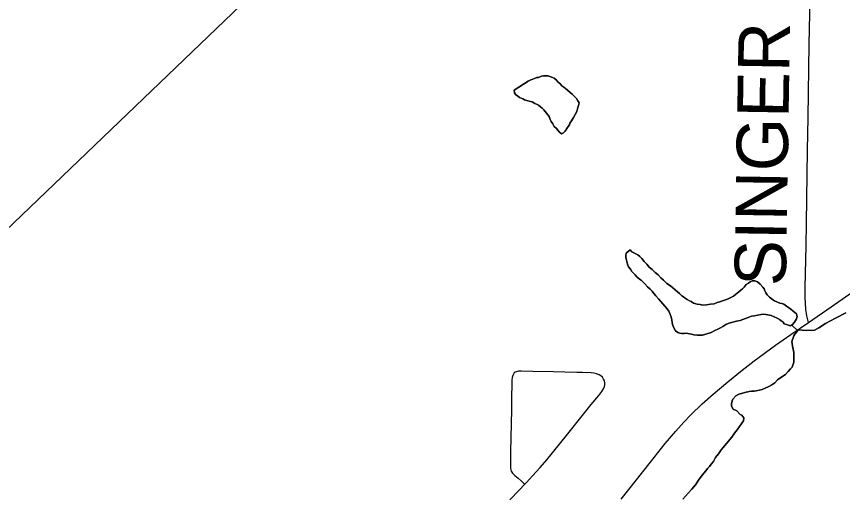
# Model space of a CAD drawing. Extents: x 0 to 34, y 0 to 22.
# Drawn here: x 23.893 to 24.806, y 14.723 to 15.253 of the extents above; entities that cross this region are included whole.
import ezdxf

# ---------------------------------------------------------------- set-up
doc = ezdxf.new("R2010")
doc.units = 0
for name, color, linetype in [('GM_X_Major_River', 7, 'Continuous'), ('GM_X_Minor_Lake', 7, 'Continuous'), ('GM_X_Minor_River', 7, 'Continuous'), ('GM_X_State_Route', 7, 'Continuous'), ('GM_X_Township_Road', 7, 'Continuous'), ('GM_X_Township_Road_Text', 7, 'Continuous')]:
    doc.layers.add(name, color=color, linetype=linetype)

msp = doc.modelspace()

# ---------------------------------------------------------------- linework, layer by layer
at = {"layer": 'GM_X_Major_River'}
for points in [[(24.81011, 14.92539), (24.79851, 14.91969), (24.78765, 14.91358), (24.78026, 14.90888), (24.77523, 14.90638), (24.77255, 14.90609), (24.76989, 14.90618), (24.76607, 14.90592), (24.7619, 14.90644), (24.7581, 14.90657), (24.75574, 14.90436), (24.75375, 14.90176), (24.75255, 14.8999), (24.75173, 14.89803), (24.75091, 14.89615), (24.75044, 14.8935), (24.75076, 14.89159), (24.75105, 14.88854), (24.75171, 14.88547), (24.75203, 14.88356), (24.75235, 14.88165), (24.75267, 14.87973), (24.75257, 14.87669), (24.75246, 14.87327), (24.75239, 14.87099), (24.75194, 14.86873), (24.75069, 14.86534), (24.74872, 14.8635), (24.74634, 14.86054), (24.74319, 14.85722), (24.7393, 14.85469), (24.73463, 14.85141), (24.73147, 14.8481), (24.72836, 14.84592), (24.72487, 14.84413), (24.72101, 14.84236), (24.71753, 14.84095), (24.71408, 14.83992), (24.71101, 14.83926), (24.70871, 14.83896), (24.70567, 14.83906), (24.70299, 14.83877), (24.69838, 14.8374), (24.69454, 14.83638), (24.69185, 14.83571), (24.68837, 14.83393), (24.6852, 14.83023), (24.68438, 14.82835), (24.68351, 14.82496), (24.68381, 14.82228), (24.68561, 14.81918), (24.68935, 14.81715), (24.69304, 14.81323), (24.69492, 14.8124), (24.69711, 14.80967), (24.697, 14.80625), (24.69502, 14.80365), (24.69261, 14.79992), (24.68983, 14.79621), (24.68704, 14.7925), (24.68385, 14.78804), (24.67237, 14.77434), (24.66918, 14.76988), (24.66601, 14.7658)], [(24.66601, 14.7658), (24.66918, 14.76988), (24.67237, 14.77434), (24.68385, 14.78804), (24.68704, 14.7925), (24.68983, 14.79621), (24.69261, 14.79992), (24.69502, 14.80365), (24.697, 14.80625), (24.69711, 14.80967), (24.69492, 14.8124), (24.69304, 14.81323), (24.68935, 14.81715), (24.68561, 14.81918), (24.68381, 14.82228), (24.68351, 14.82496), (24.68438, 14.82835), (24.6852, 14.83023), (24.68837, 14.83393), (24.69185, 14.83571), (24.69454, 14.83638), (24.69838, 14.8374), (24.70299, 14.83877), (24.70567, 14.83906), (24.70871, 14.83896), (24.71101, 14.83926), (24.71408, 14.83992), (24.71753, 14.84095), (24.72101, 14.84236), (24.72487, 14.84413), (24.72836, 14.84592), (24.73147, 14.8481), (24.73463, 14.85141), (24.7393, 14.85469), (24.74319, 14.85722), (24.74634, 14.86054), (24.74872, 14.8635), (24.75069, 14.86534), (24.75194, 14.86873), (24.75239, 14.87099), (24.75246, 14.87327), (24.75257, 14.87669), (24.75267, 14.87973), (24.75235, 14.88165), (24.75203, 14.88356), (24.75171, 14.88547), (24.75105, 14.88854), (24.75076, 14.89159), (24.75044, 14.8935), (24.75091, 14.89615), (24.75173, 14.89803), (24.75255, 14.8999), (24.75375, 14.90176), (24.75574, 14.90436), (24.7581, 14.90657), (24.7619, 14.90644), (24.76607, 14.90592), (24.76989, 14.90618), (24.77255, 14.90609), (24.77523, 14.90638), (24.78026, 14.90888), (24.78765, 14.91358), (24.79851, 14.91969), (24.81011, 14.92539)], [(24.66601, 14.7658), (24.66358, 14.76132), (24.6612, 14.75835), (24.65921, 14.75576), (24.65724, 14.75354), (24.65525, 14.75094), (24.65288, 14.74836), (24.6501, 14.74465), (24.6473, 14.74055), (24.64372, 14.73573), (24.63975, 14.73091), (24.63581, 14.72648), (24.62988, 14.71983)], [(24.62988, 14.71983), (24.63581, 14.72648), (24.63975, 14.73091), (24.64372, 14.73573), (24.6473, 14.74055), (24.6501, 14.74465), (24.65288, 14.74836), (24.65525, 14.75094), (24.65724, 14.75354), (24.65921, 14.75576), (24.6612, 14.75835), (24.66358, 14.76132), (24.66601, 14.7658)]]:
    msp.add_lwpolyline(points, dxfattribs=at)
at = {"layer": 'GM_X_Minor_Lake'}
for points in [[(24.50687, 15.13746), (24.50808, 15.13932), (24.5089, 15.1412), (24.51254, 15.14792), (24.51382, 15.15207), (24.51465, 15.15432), (24.51513, 15.15735), (24.51368, 15.15968), (24.51223, 15.16201), (24.51002, 15.16437), (24.50743, 15.16673), (24.50521, 15.16871), (24.50225, 15.17147), (24.50001, 15.17307), (24.49816, 15.17465), (24.49631, 15.17623), (24.49446, 15.1782), (24.49187, 15.18057), (24.49003, 15.18253), (24.48781, 15.18451), (24.48593, 15.18533), (24.48293, 15.18657), (24.48066, 15.18703), (24.47799, 15.18712), (24.47571, 15.18719), (24.47379, 15.18687), (24.47032, 15.18547), (24.46841, 15.18515), (24.46609, 15.18409), (24.46416, 15.18339), (24.46185, 15.18271), (24.45876, 15.18129), (24.44359, 15.17114)], [(24.44359, 15.17114), (24.45876, 15.18129), (24.46185, 15.18271), (24.46416, 15.18339), (24.46609, 15.18409), (24.46841, 15.18515), (24.47032, 15.18547), (24.47379, 15.18687), (24.47571, 15.18719), (24.47799, 15.18712), (24.48066, 15.18703), (24.48293, 15.18657), (24.48593, 15.18533), (24.48781, 15.18451), (24.49003, 15.18253), (24.49187, 15.18057), (24.49446, 15.1782), (24.49631, 15.17623), (24.49816, 15.17465), (24.50001, 15.17307), (24.50225, 15.17147), (24.50521, 15.16871), (24.50743, 15.16673), (24.51002, 15.16437), (24.51223, 15.16201), (24.51368, 15.15968), (24.51513, 15.15735), (24.51465, 15.15432), (24.51382, 15.15207), (24.51254, 15.14792), (24.5089, 15.1412), (24.50808, 15.13932), (24.50687, 15.13746), (24.50489, 15.13486), (24.50445, 15.13297), (24.50325, 15.13111), (24.50165, 15.12888), (24.49965, 15.1259), (24.49807, 15.12406), (24.49575, 15.12299), (24.49316, 15.12536), (24.49022, 15.12888), (24.48764, 15.13125), (24.4862, 15.13396), (24.48438, 15.13668), (24.48331, 15.139), (24.48227, 15.14208), (24.48081, 15.14403), (24.47935, 15.14598), (24.47641, 15.1495), (24.47457, 15.15147), (24.47271, 15.15305), (24.47048, 15.15465), (24.46824, 15.15586), (24.46636, 15.15669), (24.46336, 15.15831), (24.46147, 15.15875), (24.45845, 15.15961), (24.45505, 15.16048), (24.45319, 15.16169), (24.44943, 15.16333), (24.4472, 15.16493), (24.44533, 15.16613), (24.44388, 15.16846), (24.44359, 15.17114)], [(24.44359, 15.17114), (24.44388, 15.16846), (24.44533, 15.16613), (24.4472, 15.16493), (24.44943, 15.16333), (24.45319, 15.16169), (24.45505, 15.16048), (24.45845, 15.15961), (24.46147, 15.15875), (24.46336, 15.15831), (24.46636, 15.15669), (24.46824, 15.15586), (24.47048, 15.15465), (24.47271, 15.15305), (24.47457, 15.15147), (24.47641, 15.1495), (24.47935, 15.14598), (24.48081, 15.14403), (24.48227, 15.14208), (24.48331, 15.139), (24.48438, 15.13668), (24.4862, 15.13396), (24.48764, 15.13125), (24.49022, 15.12888), (24.49316, 15.12536), (24.49575, 15.12299), (24.49807, 15.12406), (24.49965, 15.1259), (24.50165, 15.12888), (24.50325, 15.13111), (24.50445, 15.13297), (24.50489, 15.13486), (24.50687, 15.13746)], [(24.57164, 14.99492), (24.56733, 14.99126), (24.56688, 14.98899), (24.5668, 14.98671), (24.56748, 14.98403), (24.56779, 14.98173), (24.5692, 14.97826), (24.5699, 14.97634), (24.5721, 14.9736), (24.57355, 14.97127), (24.57539, 14.96931), (24.57723, 14.96734), (24.57907, 14.96538), (24.58203, 14.96262), (24.5839, 14.96141), (24.58575, 14.95983), (24.58796, 14.95748), (24.59091, 14.95434), (24.59387, 14.95157), (24.59608, 14.94922), (24.5979, 14.94688), (24.6001, 14.94414), (24.60305, 14.941), (24.6126, 14.93003), (24.61442, 14.92731), (24.61547, 14.92461), (24.61653, 14.92191), (24.61722, 14.9196), (24.61753, 14.91731), (24.61821, 14.915), (24.61852, 14.91271), (24.61922, 14.91079), (24.61992, 14.90886), (24.62173, 14.90576), (24.62433, 14.90377), (24.62659, 14.90293), (24.62886, 14.90248), (24.63115, 14.90278), (24.63307, 14.9031), (24.63534, 14.90264), (24.63761, 14.90219), (24.6395, 14.90174), (24.64215, 14.90128), (24.64556, 14.90078), (24.64861, 14.90068), (24.65166, 14.90096), (24.65512, 14.90199)], [(24.65512, 14.90199), (24.65166, 14.90096), (24.64861, 14.90068), (24.64556, 14.90078), (24.64215, 14.90128), (24.6395, 14.90174), (24.63761, 14.90219), (24.63534, 14.90264), (24.63307, 14.9031), (24.63115, 14.90278), (24.62886, 14.90248), (24.62659, 14.90293), (24.62433, 14.90377), (24.62173, 14.90576), (24.61992, 14.90886), (24.61922, 14.91079), (24.61852, 14.91271), (24.61821, 14.915), (24.61753, 14.91731), (24.61722, 14.9196), (24.61653, 14.92191), (24.61547, 14.92461), (24.61442, 14.92731), (24.6126, 14.93003), (24.60305, 14.941), (24.6001, 14.94414), (24.5979, 14.94688), (24.59608, 14.94922), (24.59387, 14.95157), (24.59091, 14.95434), (24.58796, 14.95748), (24.58575, 14.95983), (24.5839, 14.96141), (24.58203, 14.96262), (24.57907, 14.96538), (24.57723, 14.96734), (24.57539, 14.96931), (24.57355, 14.97127), (24.5721, 14.9736), (24.5699, 14.97634), (24.5692, 14.97826), (24.56779, 14.98173), (24.56748, 14.98403), (24.5668, 14.98671), (24.56688, 14.98899), (24.56733, 14.99126), (24.57164, 14.99492)], [(24.65512, 14.90199), (24.66127, 14.90369), (24.66515, 14.90584), (24.66862, 14.90725), (24.67134, 14.90906), (24.67405, 14.91049), (24.67755, 14.91266), (24.67987, 14.91372), (24.68218, 14.91441), (24.68525, 14.91507), (24.68909, 14.91608), (24.69331, 14.91708), (24.69909, 14.91917), (24.70217, 14.92021), (24.70564, 14.92162), (24.70909, 14.92227), (24.71254, 14.92291), (24.71637, 14.92355), (24.71942, 14.92383), (24.7217, 14.92375), (24.7236, 14.92331), (24.72548, 14.92286), (24.72737, 14.92242), (24.73414, 14.91953), (24.73675, 14.91792), (24.73862, 14.91672), (24.74085, 14.91513), (24.74193, 14.91319), (24.74458, 14.91272), (24.74872, 14.91106), (24.75105, 14.91251), (24.75342, 14.91509), (24.75544, 14.91883), (24.75629, 14.92146), (24.75562, 14.92453), (24.75376, 14.92573), (24.7519, 14.92731), (24.74931, 14.92968), (24.7467, 14.93129), (24.74447, 14.93289), (24.74148, 14.93489), (24.73922, 14.93573), (24.73695, 14.93618), (24.73132, 14.93865), (24.72908, 14.94025), (24.72574, 14.94264), (24.72316, 14.94539), (24.72171, 14.94772), (24.72063, 14.94966), (24.71956, 14.95198), (24.7181, 14.95393), (24.71515, 14.95707), (24.71219, 14.95983), (24.70955, 14.96068), (24.70651, 14.96078), (24.70419, 14.95971), (24.70224, 14.95826), (24.69991, 14.95681), (24.69753, 14.95385), (24.69595, 14.952), (24.694, 14.95054), (24.69165, 14.94871), (24.68813, 14.94579), (24.68579, 14.94396), (24.68307, 14.94253), (24.67997, 14.94073), (24.67689, 14.93969), (24.67381, 14.93865), (24.67073, 14.93761), (24.66766, 14.93695), (24.66457, 14.93553), (24.66036, 14.93491), (24.65615, 14.93429), (24.65196, 14.93405), (24.64893, 14.93453), (24.64551, 14.93502), (24.64175, 14.93629), (24.63913, 14.9379), (24.63725, 14.93872), (24.63464, 14.94033), (24.63239, 14.94155), (24.63054, 14.94313), (24.62867, 14.94433), (24.62608, 14.9467), (24.62386, 14.94868), (24.61608, 14.9554), (24.61235, 14.95781), (24.60865, 14.96136), (24.60569, 14.96412), (24.60275, 14.96726), (24.59941, 14.97003), (24.59608, 14.97319), (24.59274, 14.97596), (24.59018, 14.97909), (24.58723, 14.98223), (24.58466, 14.98536), (24.58245, 14.98772), (24.58022, 14.98931), (24.57722, 14.99093), (24.57348, 14.99296), (24.57164, 14.99492)], [(24.57164, 14.99492), (24.57348, 14.99296), (24.57722, 14.99093), (24.58022, 14.98931), (24.58245, 14.98772), (24.58466, 14.98536), (24.58723, 14.98223), (24.59018, 14.97909), (24.59274, 14.97596), (24.59608, 14.97319), (24.59941, 14.97003), (24.60275, 14.96726), (24.60569, 14.96412), (24.60865, 14.96136), (24.61235, 14.95781), (24.61608, 14.9554), (24.62386, 14.94868), (24.62608, 14.9467), (24.62867, 14.94433), (24.63054, 14.94313), (24.63239, 14.94155), (24.63464, 14.94033), (24.63725, 14.93872), (24.63913, 14.9379), (24.64175, 14.93629), (24.64551, 14.93502), (24.64893, 14.93453), (24.65196, 14.93405), (24.65615, 14.93429), (24.66036, 14.93491), (24.66457, 14.93553), (24.66766, 14.93695), (24.67073, 14.93761), (24.67381, 14.93865), (24.67689, 14.93969), (24.67997, 14.94073), (24.68307, 14.94253), (24.68579, 14.94396), (24.68813, 14.94579), (24.69165, 14.94871), (24.694, 14.95054), (24.69595, 14.952), (24.69753, 14.95385), (24.69991, 14.95681), (24.70224, 14.95826), (24.70419, 14.95971), (24.70651, 14.96078), (24.70955, 14.96068), (24.71219, 14.95983), (24.71515, 14.95707), (24.7181, 14.95393), (24.71956, 14.95198), (24.72063, 14.94966), (24.72171, 14.94772), (24.72316, 14.94539), (24.72574, 14.94264), (24.72908, 14.94025), (24.73132, 14.93865), (24.73695, 14.93618), (24.73922, 14.93573), (24.74148, 14.93489), (24.74447, 14.93289), (24.7467, 14.93129), (24.74931, 14.92968), (24.7519, 14.92731), (24.75376, 14.92573), (24.75562, 14.92453), (24.75629, 14.92146), (24.75544, 14.91883), (24.75342, 14.91509), (24.75105, 14.91251), (24.74872, 14.91106), (24.74458, 14.91272), (24.74193, 14.91319), (24.74085, 14.91513), (24.73862, 14.91672), (24.73675, 14.91792), (24.73414, 14.91953), (24.72737, 14.92242), (24.72548, 14.92286), (24.7236, 14.92331), (24.7217, 14.92375), (24.71942, 14.92383), (24.71637, 14.92355), (24.71254, 14.92291), (24.70909, 14.92227), (24.70564, 14.92162), (24.70217, 14.92021), (24.69909, 14.91917), (24.69331, 14.91708), (24.68909, 14.91608), (24.68525, 14.91507), (24.68218, 14.91441), (24.67987, 14.91372), (24.67755, 14.91266), (24.67405, 14.91049), (24.67134, 14.90906), (24.66862, 14.90725), (24.66515, 14.90584), (24.66127, 14.90369), (24.65512, 14.90199)]]:
    msp.add_lwpolyline(points, dxfattribs=at)
at = {"layer": 'GM_X_Minor_River'}
for p, q in [((23.51667, 14.66697), (25.12417, 16.20645)), ((24.75016, 14.91194), (24.75696, 14.9055))]:
    msp.add_line(p, q, dxfattribs=at)
at = {"layer": 'GM_X_State_Route'}
msp.add_lwpolyline([(24.56172, 14.71971), (24.59428, 14.7606), (24.61049, 14.78101), (24.62208, 14.79487), (24.63078, 14.80464), (24.63851, 14.81278), (24.65114, 14.82481), (24.66325, 14.83556), (24.67943, 14.84918), (24.69537, 14.86214), (24.70866, 14.87243), (24.73228, 14.88966), (24.74915, 14.90136), (24.76861, 14.91477), (24.7937, 14.93204), (24.81816, 14.94913)], dxfattribs=at)
at = {"layer": 'GM_X_Township_Road'}
for points in [[(24.76861, 14.91477), (24.76689, 14.92196), (24.76573, 14.92936), (24.76523, 14.93594), (24.76494, 14.94287), (24.76498, 14.95344), (24.76615, 14.99945), (24.76645, 15.02432), (24.76751, 15.10517), (24.76837, 15.14124), (24.76961, 15.22209), (24.77211, 15.33962), (24.77246, 15.35766), (24.77329, 15.39746), (24.77349, 15.40803), (24.77361, 15.41489)], [(24.43856, 14.71901), (24.44899, 14.72966), (24.45511, 14.73617), (24.45706, 14.73825), (24.4638, 14.74558), (24.4723, 14.75462), (24.47963, 14.76304), (24.50141, 14.79016), (24.52007, 14.81345), (24.52865, 14.8241), (24.53699, 14.83411), (24.5404, 14.83848), (24.5423, 14.84149), (24.54337, 14.84418), (24.54373, 14.84585), (24.5438, 14.84812), (24.5433, 14.85031), (24.54235, 14.85239), (24.54101, 14.85425), (24.5393, 14.85578), (24.53731, 14.85697), (24.53455, 14.85806), (24.53167, 14.85879), (24.52872, 14.8592), (24.51879, 14.8595), (24.51261, 14.85968), (24.49956, 14.85987), (24.4871, 14.86029), (24.46412, 14.86074), (24.45113, 14.86122), (24.44816, 14.86103), (24.44592, 14.86049), (24.44443, 14.85978), (24.4436, 14.85913), (24.44261, 14.85788), (24.4419, 14.85638), (24.44129, 14.85415), (24.44105, 14.8512), (24.44062, 14.82791), (24.44044, 14.81877), (24.43986, 14.78747), (24.43958, 14.77231), (24.43945, 14.76542), (24.43942, 14.7636), (24.43935, 14.76122), (24.43928, 14.75646), (24.43936, 14.75416), (24.43979, 14.75197), (24.44031, 14.75046), (24.44156, 14.74853), (24.44405, 14.74603), (24.44781, 14.74279), (24.45104, 14.73986), (24.45465, 14.73667)]]:
    msp.add_lwpolyline(points, dxfattribs=at)

# ---------------------------------------------------------------- texts
at = {"layer": 'GM_X_Township_Road_Text'}
msp.add_text('SINGER', height=0.056818, rotation=89.05428, dxfattribs=at).set_placement((24.74362, 14.95467))

doc.saveas('drawing.dxf')
